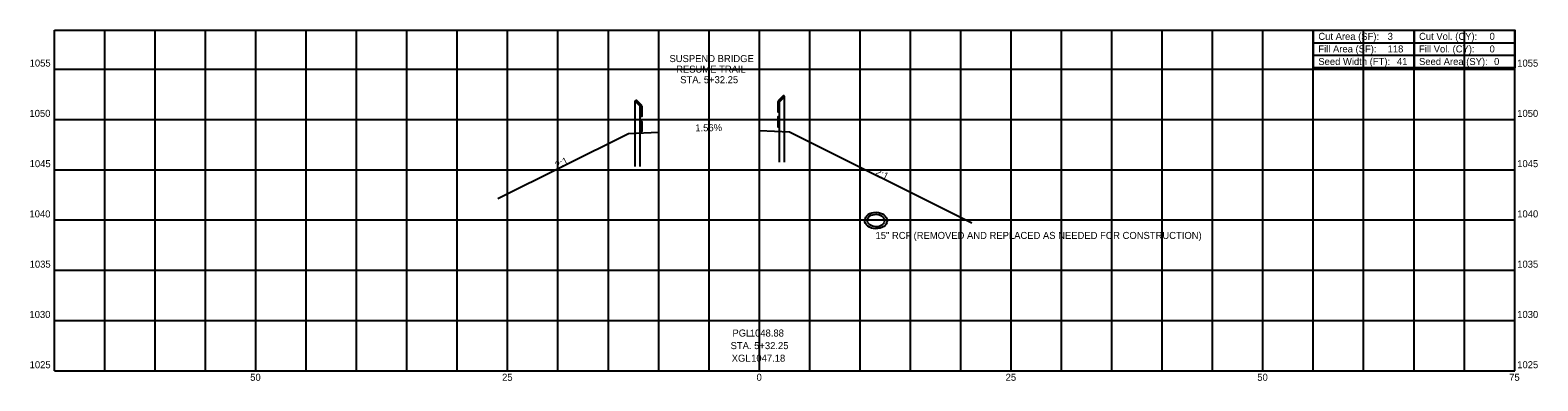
# Model space of a CAD drawing. Extents: x -72 to 77, y 1024 to 1059.
import ezdxf

# ---------------------------------------------------------------- set-up
doc = ezdxf.new("R2010")
doc.units = 0
for name, color, linetype in [('BR_P_Sub_Deep_Centerline', 7, 'Continuous'), ('BR_P_Sub_Foot_Hidden', 7, 'Continuous'), ('Default', 7, 'Continuous'), ('SC_Scratch1', 7, 'Continuous'), ('SH_Data', 7, 'Continuous'), ('SH_Major_Grid_Line', 7, 'Continuous'), ('SH_Masking', 7, 'Continuous'), ('SH_Text', 7, 'Continuous')]:
    doc.layers.add(name, color=color, linetype=linetype)

msp = doc.modelspace()

# ---------------------------------------------------------------- linework, layer by layer
at = {"layer": 'BR_P_Sub_Deep_Centerline'}
for major_axis, ratio in [((-1.11, 0.03), 0.737484), ((-0.847, 0.022), 0.737229)]:
    msp.add_ellipse((11.57, 1039.94), major_axis=major_axis, ratio=ratio, dxfattribs=at)
at = {"layer": 'BR_P_Sub_Foot_Hidden'}
for p, q in [((-12.33, 1045.3), (-12.33, 1051.8)), ((-11.83, 1051.3), (-12.33, 1051.8)), ((-11.83, 1045.3), (-11.83, 1051.3)), ((2, 1051.76), (2.5, 1052.26)), ((2, 1045.76), (2, 1051.76)), ((2.5, 1045.76), (2.5, 1052.26)), ((-11.83, 1048.3), (-11.83, 1048.3)), ((2, 1048.76), (2, 1048.76))]:
    msp.add_line(p, q, dxfattribs=at)
for points in [[(-11.83, 1051.3), (-12.33, 1051.8), (-12.22, 1051.91), (-11.72, 1051.41)], [(-11.83, 1051.3), (-11.67, 1051.3), (-11.67, 1050.3), (-11.83, 1050.3)], [(2, 1051.76), (1.83, 1051.76), (1.83, 1050.76), (2, 1050.76)], [(2, 1051.76), (2.49, 1052.26), (2.38, 1052.37), (1.89, 1051.87)], [(-11.83, 1049.8), (-11.67, 1049.8), (-11.67, 1048.8), (-11.83, 1048.8)], [(2, 1050.26), (1.83, 1050.26), (1.83, 1049.26), (2, 1049.26)]]:
    msp.add_lwpolyline(points, close=True, dxfattribs=at)
at = {"layer": 'Default'}
msp.add_circle((75, 1058.88), 0.000417, dxfattribs=at)
msp.add_circle((75, 1058.88), 0.000417, dxfattribs=at)
msp.add_circle((75, 1058.88), 0.000417, dxfattribs=at)
msp.add_circle((75, 1058.88), 0.000417, dxfattribs=at)
msp.add_circle((75, 1058.88), 0.000417, dxfattribs=at)
msp.add_circle((75, 1058.88), 0.000417, dxfattribs=at)
msp.add_circle((75, 1058.88), 0.000417, dxfattribs=at)
msp.add_circle((75, 1058.88), 0.000417, dxfattribs=at)
msp.add_circle((75, 1058.88), 0.000417, dxfattribs=at)
msp.add_circle((75, 1058.88), 0.000417, dxfattribs=at)
msp.add_circle((75, 1058.88), 0.000417, dxfattribs=at)
msp.add_circle((75, 1058.88), 0.000417, dxfattribs=at)
at = {"layer": 'SC_Scratch1'}
for points in [[(-25.97, 1042.12), (-13, 1048.61), (-10, 1048.73)], [(0, 1048.88), (3, 1048.76), (21.08, 1039.72)]]:
    msp.add_lwpolyline(points, dxfattribs=at)
at = {"layer": 'SH_Data'}
for p, q in [((55, 1058.88), (75, 1058.88)), ((55, 1058.88), (55, 1056.38)), ((65, 1058.88), (65, 1055.13)), ((75, 1058.88), (75, 1056.38)), ((55, 1057.63), (75, 1057.63)), ((55, 1056.38), (75, 1056.38)), ((63.3, 1055.76), (63.3, 1055.76)), ((72.95, 1055.76), (72.95, 1055.76))]:
    msp.add_line(p, q, dxfattribs=at)
msp.add_lwpolyline([(55, 1056.38), (55, 1055.13), (75, 1055.13), (75, 1056.38)], dxfattribs=at)
at = {"layer": 'SH_Major_Grid_Line'}
for p, q in [((-70, 1058.88), (75, 1058.88)), ((-70, 1025), (-70, 1058.88)), ((-65, 1025), (-65, 1058.88)), ((-60, 1025), (-60, 1058.88)), ((-55, 1025), (-55, 1058.88)), ((-50, 1025), (-50, 1058.88)), ((-45, 1025), (-45, 1058.88)), ((-40, 1025), (-40, 1058.88)), ((-35, 1025), (-35, 1058.88)), ((-30, 1025), (-30, 1058.88)), ((-25, 1025), (-25, 1058.88)), ((-20, 1025), (-20, 1058.88)), ((-15, 1025), (-15, 1058.88)), ((-10, 1025), (-10, 1058.88)), ((-5, 1025), (-5, 1058.88)), ((0, 1025), (0, 1058.88)), ((5, 1025), (5, 1058.88)), ((10, 1025), (10, 1058.88)), ((15, 1025), (15, 1058.88)), ((20, 1025), (20, 1058.88)), ((25, 1025), (25, 1058.88)), ((30, 1025), (30, 1058.88)), ((35, 1025), (35, 1058.88)), ((40, 1025), (40, 1058.88)), ((45, 1025), (45, 1058.88)), ((50, 1025), (50, 1058.88)), ((55, 1025), (55, 1058.88)), ((60, 1025), (60, 1058.88)), ((65, 1025), (65, 1058.88)), ((70, 1025), (70, 1058.88)), ((75, 1025), (75, 1058.88)), ((-70, 1055), (75, 1055)), ((-70, 1050), (75, 1050)), ((-70, 1045), (75, 1045)), ((-70, 1040), (75, 1040)), ((-70, 1035), (75, 1035)), ((-70, 1030), (75, 1030)), ((-70, 1025), (75, 1025))]:
    msp.add_line(p, q, dxfattribs=at)
at = {"layer": 'SH_Masking'}
msp.add_lwpolyline([(55, 1058.88), (75, 1058.88), (75, 1055.13), (55, 1055.13)], close=True, dxfattribs=at)

# ---------------------------------------------------------------- texts
at = {"layer": 'SH_Text'}
for s, p in [('Cut Area (SF):', (55.5, 1057.91)), ('3', (62.38, 1057.91)), ('Cut Vol. (CY):', (65.5, 1057.91)), ('0', (72.5, 1057.91)), ('Fill Area (SF):', (55.5, 1056.66)), ('118', (62.38, 1056.66)), ('Fill Vol. (CY):', (65.5, 1056.66)), ('0', (72.5, 1056.66)), ('1055', (-72.46, 1055.25)), ('SUSPEND BRIDGE', (-8.93, 1055.7)), ('Seed Width (FT):', (55.5, 1055.41)), ('41', (63.3, 1055.41)), ('Seed Area (SY):', (65.5, 1055.41)), ('0', (72.95, 1055.41)), ('1055', (75.25, 1055.25)), ('RESUME TRAIL', (-8.27, 1054.65)), ('STA. 5+32.25', (-7.86, 1053.6)), ('1050', (-72.48, 1050.25)), ('1050', (75.25, 1050.25)), ('1045', (-72.46, 1045.25)), ('1045', (75.25, 1045.25)), ('1040', (-72.48, 1040.25)), ('1040', (75.25, 1040.25)), ('15" RCP', (11.53, 1038.11)), (' (REMOVED AND REPLACED AS NEEDED FOR CONSTRUCTION)', (15.05, 1038.11)), ('1035', (-72.46, 1035.25)), ('1035', (75.25, 1035.25)), ('1030', (-72.48, 1030.25)), ('1030', (75.25, 1030.25)), ('PGL', (-2.68, 1028.4)), ('1048.88', (-0.95, 1028.4)), ('STA. 5+32.25', (-2.86, 1027.15)), ('1025', (-72.46, 1025.25)), ('XGL ', (-2.75, 1025.9)), ('1047.18', (-0.82, 1025.9)), ('1025', (75.25, 1025.25)), ('50', (-50.56, 1024)), ('25', (-25.55, 1024)), ('0', (-0.28, 1024)), ('25', (24.45, 1024)), ('50', (49.44, 1024)), ('75', (74.45, 1024))]:
    msp.add_text(s, height=0.7, dxfattribs=at).set_placement(p)
for s, rotation, p in [('1.56%', 0.8937, (-6.36, 1048.8)), ('2:1', 26.5651, (-20.07, 1045.08)), ('2:1', 333.4349, (11.45, 1044.54))]:
    msp.add_text(s, height=0.7, rotation=rotation, dxfattribs=at).set_placement(p)

doc.saveas('drawing.dxf')
